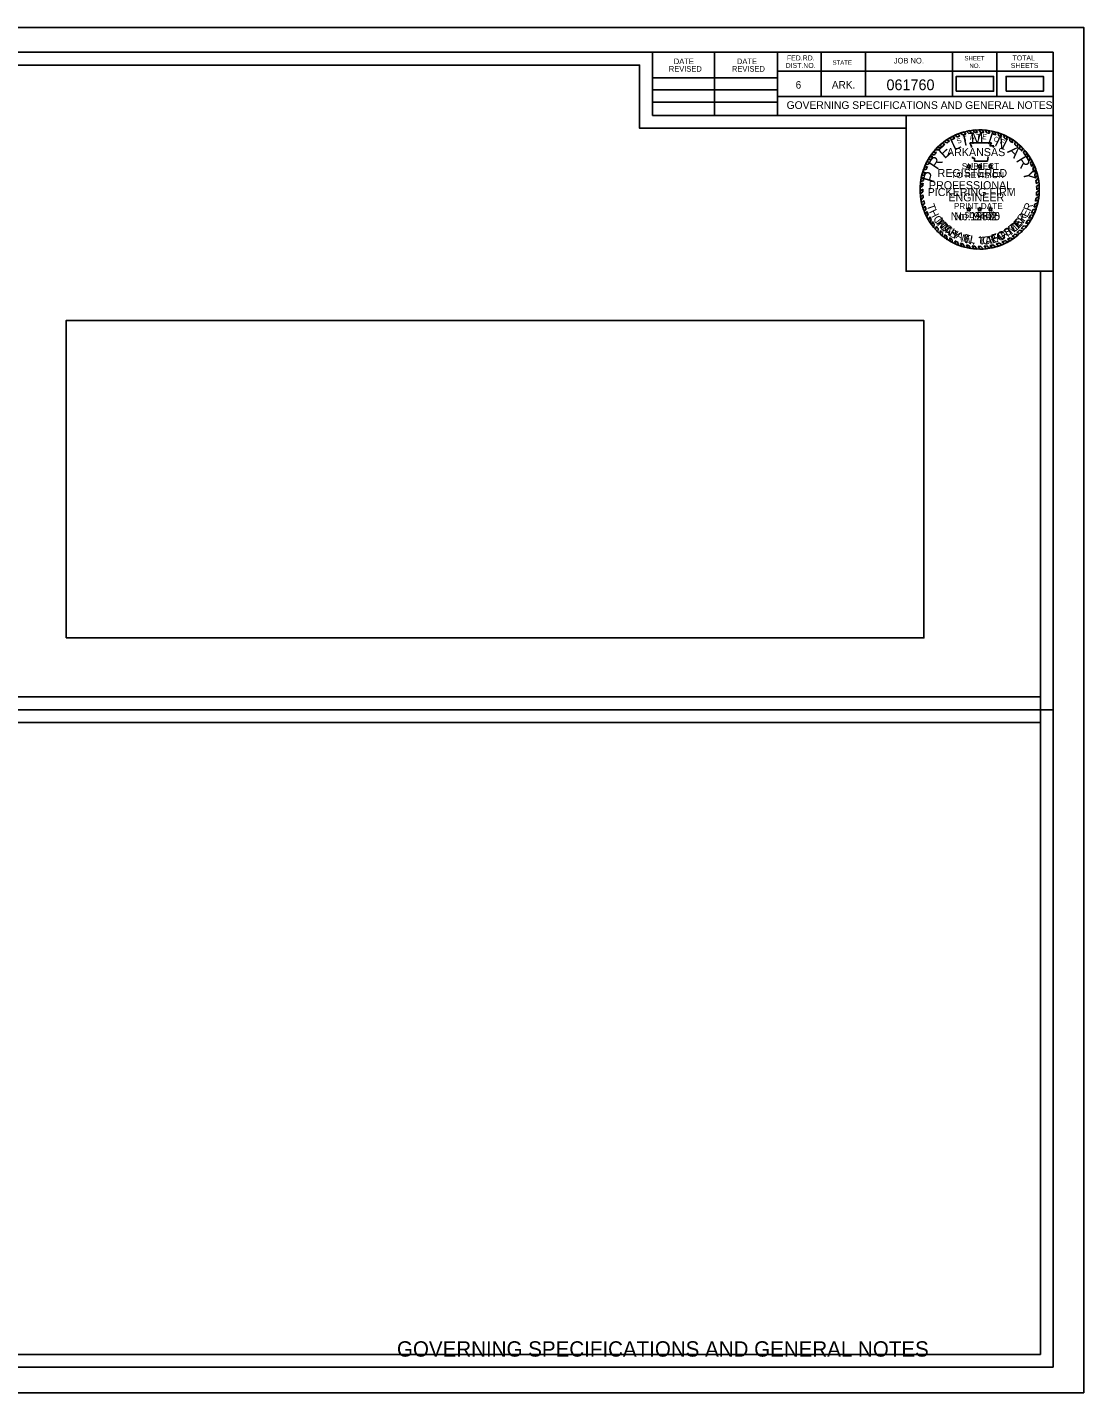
# Model space of a CAD drawing. Extents: x -12 to 321, y -4 to 209.
# Drawn here: x 155.9 to 320.9, y -4 to 209.4 of the extents above; entities that cross this region are included whole.
import ezdxf

# ---------------------------------------------------------------- set-up
doc = ezdxf.new("R2010")
doc.units = 0
for name, color, linetype in [('Default', 7, 'Continuous'), ('R_Border', 7, 'Continuous'), ('R_Border Notes', 7, 'Continuous'), ('R_Border Plan-Plan', 7, 'Continuous'), ('R_Border Title', 7, 'Continuous'), ('R_No Plot', 7, 'Continuous'), ('STAMP_PE_CRAFTON', 7, 'Continuous'), ('STAMP_PE_FOSTER', 7, 'Continuous'), ('STAMP_PE_SEAL-INFO', 7, 'Continuous'), ('STAMP_PE_TAEGTMEYER', 7, 'Continuous'), ('STAMP_PE_TXT', 7, 'Continuous'), ('STAMP_PRELIMINARY', 7, 'Continuous')]:
    doc.layers.add(name, color=color, linetype=linetype)

msp = doc.modelspace()

# ---------------------------------------------------------------- linework, layer by layer
at = {"layer": 'Default'}
for points in [[(301.02, 199.37), (306.86, 199.37), (306.86, 201.68), (301.02, 201.68)], [(308.8, 199.37), (314.64, 199.37), (314.64, 201.68), (308.8, 201.68)], [(161.91, 113.95), (295.96, 113.95), (295.96, 163.53), (161.91, 163.53)]]:
    msp.add_lwpolyline(points, close=True, dxfattribs=at)
at = {"layer": 'R_Border'}
for p, q in [((0, 205.46), (316.18, 205.46)), ((253.54, 195.58), (253.54, 205.46)), ((263.22, 195.58), (263.22, 205.46)), ((273.08, 205.46), (273.08, 195.58)), ((279.92, 205.46), (279.92, 198.52)), ((286.86, 205.46), (286.86, 198.52)), ((300.44, 205.46), (300.44, 198.52)), ((307.38, 205.46), (307.38, 198.52)), ((316.18, 0), (316.18, 205.46)), ((253.54, 201.44), (273.08, 201.44)), ((316.18, 202.52), (273.08, 202.52)), ((316.18, 202.54), (316.18, 202.54)), ((253.54, 199.58), (273.08, 199.58)), ((316.18, 198.52), (273.08, 198.52)), ((276.04, 198.52), (316.18, 198.52)), ((253.54, 197.64), (273.08, 197.64)), ((316.18, 195.58), (253.54, 195.58)), ((316.18, 0), (0, 0))]:
    msp.add_line(p, q, dxfattribs=at)
at = {"layer": 'R_Border Plan-Plan'}
msp.add_line((0, 102.73), (316.18, 102.73), dxfattribs=at)
at = {"layer": 'R_No Plot'}
for points in [[(-12.41, 209.35), (320.93, 209.35), (320.93, -3.98), (-12.41, -3.98)], [(314.18, 104.73), (2, 104.73), (2, 203.46), (251.54, 203.46), (251.54, 193.58), (269.08, 193.58), (293.18, 193.58), (293.18, 171.25), (314.18, 171.25)], [(2, 203.46), (251.54, 203.46), (251.54, 193.58), (269.08, 193.58), (293.18, 193.58), (293.18, 171.25), (314.18, 171.25), (314.18, 2), (2, 2)], [(293.18, 195.58), (316.18, 195.58), (316.18, 171.25), (293.18, 171.25)], [(2, 100.73), (314.18, 100.73), (314.18, 2), (2, 2)]]:
    msp.add_lwpolyline(points, close=True, dxfattribs=at)
at = {"layer": 'STAMP_PE_SEAL-INFO'}
for p, q in [((299.9, 192.03), (300.34, 191.81)), ((300.35, 192.28), (300.82, 192.06)), ((300.78, 192.49), (301.17, 192.22)), ((301.29, 192.71), (301.59, 192.38)), ((301.64, 192.84), (302.02, 192.53)), ((302.23, 193.02), (302.52, 192.67)), ((302.62, 193.11), (302.97, 192.77)), ((303.1, 193.21), (303.4, 192.84)), ((303.62, 193.28), (303.9, 192.9)), ((304.35, 192.93), (304.04, 193.32)), ((304.85, 192.93), (304.57, 193.34)), ((305.31, 192.91), (305.05, 193.34)), ((305.81, 192.86), (305.52, 193.31)), ((306.24, 192.8), (305.98, 193.25)), ((306.8, 192.68), (306.63, 193.14)), ((307.2, 192.57), (307.04, 193.04)), ((307.65, 192.42), (307.51, 192.9)), ((308.07, 192.26), (307.93, 192.76)), ((308.53, 192.06), (308.43, 192.56)), ((308.98, 191.83), (308.89, 192.34)), ((309.37, 191.6), (309.33, 192.1)), ((297.72, 190.22), (298.24, 190.19)), ((298.04, 190.57), (298.59, 190.53)), ((298.38, 190.89), (298.84, 190.75)), ((298.72, 191.19), (299.25, 191.09)), ((299.1, 191.52), (299.55, 191.31)), ((299.52, 191.79), (299.96, 191.58)), ((303.15, 191.31), (306.5, 191.31)), ((303.27, 191.01), (303.15, 191.31)), ((303.38, 190.71), (303.27, 191.01)), ((303.39, 190.59), (303.38, 190.71)), ((306.5, 191.31), (306.27, 190.82)), ((306.27, 190.82), (306.9, 190.82)), ((306.9, 190.82), (306.76, 190.59)), ((309.8, 191.32), (309.77, 191.83)), ((310.16, 191.05), (310.2, 191.54)), ((310.61, 190.68), (310.63, 191.2)), ((310.92, 190.39), (310.99, 190.88)), ((311.28, 190.01), (311.35, 190.54)), ((311.55, 189.7), (311.69, 190.17)), ((296.2, 187.89), (296.7, 187.99)), ((296.38, 188.27), (296.88, 188.34)), ((296.61, 188.7), (297.1, 188.72)), ((296.86, 189.1), (297.38, 189.13)), ((297.1, 189.44), (297.6, 189.44)), ((297.37, 189.81), (297.92, 189.83)), ((303.58, 188.89), (303.55, 189.1)), ((303.89, 188.89), (303.58, 188.89)), ((303.89, 188.46), (303.89, 188.89)), ((305.92, 188.46), (303.89, 188.46)), ((305.94, 188.79), (305.92, 188.46)), ((306.01, 189.1), (305.94, 188.79)), ((311.88, 189.28), (312.01, 189.78)), ((312.1, 188.96), (312.28, 189.43)), ((312.41, 188.47), (312.59, 188.96)), ((312.61, 188.1), (312.83, 188.54)), ((312.84, 187.62), (313.06, 188.1)), ((295.96, 185.89), (295.5, 185.64)), ((295.6, 186.14), (296.07, 186.33)), ((295.7, 186.54), (296.18, 186.71)), ((295.86, 187.05), (296.35, 187.18)), ((296.01, 187.45), (296.52, 187.6)), ((312.98, 187.28), (313.24, 187.71)), ((313.17, 186.73), (313.44, 187.2)), ((313.28, 186.37), (313.57, 186.82)), ((313.41, 185.81), (313.73, 186.25)), ((313.48, 185.43), (313.84, 185.78)), ((295.78, 184.57), (295.36, 184.31)), ((295.77, 184.08), (295.36, 183.74)), ((295.82, 185), (295.38, 184.71)), ((295.77, 183.67), (295.38, 183.35)), ((295.88, 185.43), (295.43, 185.21)), ((313.55, 184.92), (313.92, 185.25)), ((313.58, 184.5), (313.97, 184.79)), ((313.58, 183.58), (314, 183.85)), ((313.59, 183.98), (314, 184.3)), ((295.81, 183.18), (295.44, 182.82)), ((295.86, 182.75), (295.5, 182.37)), ((295.94, 182.29), (295.6, 181.92)), ((296.03, 181.87), (295.72, 181.45)), ((296.15, 181.42), (295.86, 181)), ((313.15, 181.24), (313.64, 181.44)), ((313.29, 181.73), (313.77, 181.93)), ((313.4, 182.18), (313.86, 182.38)), ((313.49, 182.68), (313.93, 182.9)), ((313.54, 183.07), (313.98, 183.33)), ((296.3, 181), (296.01, 180.59)), ((296.46, 180.57), (296.2, 180.15)), ((296.63, 180.19), (296.41, 179.73)), ((296.87, 179.73), (296.68, 179.24)), ((297.1, 179.33), (296.92, 178.86)), ((312.19, 179.23), (312.67, 179.22)), ((312.36, 179.51), (312.87, 179.56)), ((312.64, 180), (313.12, 180.07)), ((312.8, 180.34), (313.29, 180.44)), ((313.01, 180.86), (313.49, 180.99)), ((297.31, 179.01), (297.2, 178.46)), ((297.59, 178.62), (297.49, 178.09)), ((297.89, 178.25), (297.8, 177.73)), ((298.19, 177.91), (298.13, 177.39)), ((298.52, 177.58), (298.49, 177.05)), ((298.86, 177.27), (298.86, 176.74)), ((310.5, 177.27), (310.97, 177.14)), ((310.91, 177.64), (311.35, 177.51)), ((311.16, 177.9), (311.64, 177.82)), ((311.55, 178.34), (312.01, 178.26)), ((311.85, 178.73), (312.36, 178.73)), ((299.22, 176.98), (299.24, 176.45)), ((299.56, 176.73), (299.6, 176.21)), ((299.99, 176.45), (300.05, 175.93)), ((300.34, 176.24), (300.43, 175.73)), ((300.82, 175.99), (300.97, 175.47)), ((301.19, 175.82), (301.36, 175.31)), ((301.68, 175.63), (301.89, 175.13)), ((302.09, 175.49), (302.32, 175)), ((302.6, 175.36), (302.81, 174.89)), ((303, 175.27), (303.24, 174.81)), ((303.5, 175.19), (303.74, 174.75)), ((303.93, 175.14), (304.21, 174.71)), ((304.42, 175.11), (304.72, 174.7)), ((304.88, 175.11), (305.22, 174.72)), ((305.4, 175.14), (305.72, 174.76)), ((305.84, 175.18), (306.21, 174.83)), ((306.28, 175.25), (306.67, 174.91)), ((306.77, 175.36), (307.15, 175.03)), ((307.23, 175.48), (307.65, 175.19)), ((307.73, 175.65), (308.17, 175.38)), ((308.14, 175.81), (308.57, 175.55)), ((308.6, 176.02), (309.09, 175.81)), ((309.01, 176.23), (309.43, 176)), ((309.43, 176.48), (309.88, 176.28)), ((309.77, 176.71), (310.21, 176.52)), ((310.23, 177.05), (310.7, 176.9))]:
    msp.add_line(p, q, dxfattribs=at)
for radius, start, end in [(9.32, 117.6544, 120.8099), (8.91, 115.6869, 119.1583), (9.32, 111.3124, 114.7026), (8.91, 110.3086, 113.1659), (9.32, 105.2339, 109.0352), (8.91, 104.0352, 107.3615), (9.32, 99.7525, 102.7765), (8.91, 98.258, 101.0329), (9.32, 93.9381, 96.5517), (8.91, 92.1102, 95.0367), (9.32, 87.7298, 90.6707), (8.91, 85.9628, 88.9097), (9.32, 81.9732, 84.8236), (8.91, 79.9264, 82.696), (9.32, 75.3125, 77.9426), (8.91, 73.5575, 76.2314), (9.32, 69.6061, 72.3058), (8.91, 67.6248, 70.504), (9.32, 63.1329, 66.2704), (8.91, 61.1558, 64.3784), (9.32, 56.9003, 60.0942), (9.32, 135.4021, 138.3031), (8.91, 133.1331, 136.2562), (9.32, 129.7326, 132.5376), (8.91, 127.5297, 130.9683), (9.32, 123.6199, 126.5906), (8.91, 121.9746, 125.11), (8.91, 54.9238, 58.2702), (8.91, 48.3016, 52.0395), (9.32, 50.3492, 53.7159), (8.91, 42.2212, 45.5512), (9.32, 44.3405, 47.3929), (9.32, 38.1247, 41.2316), (9.32, 152.864, 155.5189), (9.32, 147.0072, 149.899), (8.91, 151.0315, 153.573), (9.32, 141.6056, 144.4486), (8.91, 145.0197, 148.2104), (8.91, 139.301, 142.5873), (8.91, 36.135, 39.5311), (8.91, 29.9032, 33.6645), (9.32, 31.9614, 35.4294), (8.91, 23.7732, 27.2211), (9.32, 25.9391, 29.0125), (9.32, 170.0003, 172.6878), (9.32, 164.3068, 166.894), (9.32, 158.4077, 161.0701), (8.91, 167.9048, 170.9039), (8.91, 162.4331, 165.0013), (8.91, 156.3402, 159.2319), (8.91, 17.6802, 21.4251), (9.32, 19.9538, 23.3141), (8.91, 11.5444, 15.2364), (9.32, 13.8421, 17.4447), (9.32, 7.5852, 10.8621), (9.32, 175.7409, 178.2066), (9.32, 181.7251, 184.1626), (8.91, 179.6454, 182.2633), (8.91, 173.73, 176.4734), (8.91, 5.7599, 9.0606), (8.91, 353.8632, 357.1274), (8.91, 359.7329, 3.0639), (9.32, 1.7215, 4.7268), (9.32, 355.7156, 358.9569), (9.32, 187.4204, 190.1927), (9.32, 193.0369, 195.9973), (8.91, 185.4539, 188.234), (8.91, 191.2274, 193.9858), (8.91, 196.9675, 199.8353), (8.91, 341.777, 345.0925), (8.91, 348.0778, 351.3435), (9.32, 343.8925, 347.035), (9.32, 349.8305, 353.0885), (9.32, 198.8967, 201.6281), (9.32, 204.5479, 207.4328), (8.91, 202.7761, 205.4791), (9.32, 210.8636, 213.6571), (8.91, 208.7883, 211.7934), (8.91, 323.5851, 327.4407), (8.91, 329.5549, 333.2076), (9.32, 325.4405, 328.9872), (8.91, 335.6038, 339.1858), (9.32, 331.4037, 334.9332), (9.32, 337.3837, 340.9933), (9.32, 216.6115, 219.491), (8.91, 214.1838, 217.2747), (9.32, 222.48, 225.3801), (8.91, 220.3909, 223.3056), (8.91, 226.2494, 229.2407), (8.91, 310.7744, 314.3161), (9.32, 312.4518, 315.6633), (8.91, 316.6531, 320.3711), (9.32, 318.2846, 321.8043), (9.32, 228.3665, 231.348), (8.91, 232.229, 234.9336), (9.32, 234.295, 236.9452), (8.91, 238.2223, 240.8353), (9.32, 240.1977, 242.8613), (8.91, 244.3204, 246.9486), (9.32, 246.576, 249.1558), (8.91, 250.3491, 253.1216), (9.32, 252.5967, 255.3252), (8.91, 256.505, 259.1192), (8.91, 262.3783, 265.2012), (8.91, 268.3215, 271.277), (8.91, 274.6157, 277.4486), (8.91, 280.3459, 283.5814), (9.32, 282.3199, 285.3702), (8.91, 286.6423, 289.9783), (9.32, 288.5709, 291.9733), (8.91, 292.8745, 296.1185), (9.32, 294.6481, 298.2166), (8.91, 299.0768, 302.1724), (9.32, 300.621, 303.8703), (8.91, 304.823, 308.5143), (9.32, 306.3721, 310.208), (9.32, 258.4433, 261.1398), (9.32, 264.1978, 267.1009), (9.32, 270.2548, 273.3361), (9.32, 276.4239, 279.4357)]:
    msp.add_arc((304.68, 184.02), radius, start, end, dxfattribs=at)
at = {"layer": 'STAMP_PE_TXT'}
for p, q in [((302.86, 187.59), (302.66, 187.74)), ((302.66, 187.74), (302.91, 187.74)), ((302.91, 187.74), (302.98, 187.97)), ((302.98, 187.97), (303.06, 187.74)), ((303.06, 187.74), (303.3, 187.74)), ((303.3, 187.74), (303.1, 187.59)), ((304.56, 187.59), (304.36, 187.74)), ((304.36, 187.74), (304.6, 187.74)), ((304.6, 187.74), (304.68, 187.97)), ((304.68, 187.97), (304.76, 187.74)), ((304.76, 187.74), (305, 187.74)), ((305, 187.74), (304.8, 187.59)), ((306.26, 187.59), (306.06, 187.74)), ((306.06, 187.74), (306.3, 187.74)), ((306.3, 187.74), (306.38, 187.97)), ((306.38, 187.97), (306.45, 187.74)), ((306.45, 187.74), (306.7, 187.74)), ((306.7, 187.74), (306.5, 187.59)), ((302.78, 187.36), (302.86, 187.59)), ((302.98, 187.5), (302.78, 187.36)), ((303.18, 187.36), (302.98, 187.5)), ((303.1, 187.59), (303.18, 187.36)), ((304.48, 187.36), (304.56, 187.59)), ((304.68, 187.5), (304.48, 187.36)), ((304.88, 187.36), (304.68, 187.5)), ((304.8, 187.59), (304.88, 187.36)), ((306.18, 187.36), (306.26, 187.59)), ((306.38, 187.5), (306.18, 187.36)), ((306.58, 187.36), (306.38, 187.5)), ((306.5, 187.59), (306.58, 187.36)), ((302.86, 180.89), (302.66, 181.03)), ((302.66, 181.03), (302.91, 181.03)), ((302.78, 180.65), (302.86, 180.89)), ((302.98, 180.8), (302.78, 180.65)), ((302.91, 181.03), (302.98, 181.26)), ((302.98, 181.26), (303.06, 181.03)), ((303.18, 180.65), (302.98, 180.8)), ((303.06, 181.03), (303.3, 181.03)), ((303.3, 181.03), (303.1, 180.89)), ((303.1, 180.89), (303.18, 180.65)), ((304.56, 180.89), (304.36, 181.03)), ((304.36, 181.03), (304.6, 181.03)), ((304.48, 180.65), (304.56, 180.89)), ((304.68, 180.8), (304.48, 180.65)), ((304.6, 181.03), (304.68, 181.26)), ((304.68, 181.26), (304.76, 181.03)), ((304.88, 180.65), (304.68, 180.8)), ((304.76, 181.03), (305, 181.03)), ((305, 181.03), (304.8, 180.89)), ((304.8, 180.89), (304.88, 180.65)), ((306.26, 180.89), (306.06, 181.03)), ((306.06, 181.03), (306.3, 181.03)), ((306.18, 180.65), (306.26, 180.89)), ((306.38, 180.8), (306.18, 180.65)), ((306.3, 181.03), (306.38, 181.26)), ((306.38, 181.26), (306.45, 181.03)), ((306.58, 180.65), (306.38, 180.8)), ((306.45, 181.03), (306.7, 181.03)), ((306.7, 181.03), (306.5, 180.89)), ((306.5, 180.89), (306.58, 180.65))]:
    msp.add_line(p, q, dxfattribs=at)
at = {"layer": 'STAMP_PRELIMINARY'}
msp.add_circle((304.68, 184.02), 9.32, dxfattribs=at)

# ---------------------------------------------------------------- texts
at = {"layer": 'R_Border'}
for s, height, p in [('FED.RD.', 0.782, (274.56, 204.18)), ('SHEET', 0.684, (302.3, 204.18)), ('TOTAL', 0.782, (309.82, 204.18)), ('REVISED', 0.879, (256.1, 202.42)), ('DATE', 0.879, (256.88, 203.6)), ('REVISED', 0.879, (265.96, 202.42)), ('DATE', 0.879, (266.74, 203.6)), ('DIST.NO.', 0.782, (274.36, 203)), ('STATE', 0.684, (281.68, 203.5)), ('JOB NO.', 0.879, (291.26, 203.7)), ('NO.', 0.684, (303.08, 203)), ('SHEETS', 0.782, (309.54, 203)), ('6', 1.17, (275.92, 199.78)), ('ARK.', 1.172, (281.58, 199.78))]:
    msp.add_text(s, height=height, dxfattribs=at).set_placement(p)
at = {"layer": 'R_Border Notes'}
for s, height, p in [('061760', 1.68, (290.12, 199.53)), ('GOVERNING SPECIFICATIONS AND GENERAL NOTES', 1.2, (274.51, 196.6))]:
    msp.add_text(s, height=height, dxfattribs=at).set_placement(p)
at = {"layer": 'R_Border Title'}
msp.add_text('GOVERNING SPECIFICATIONS AND GENERAL NOTES', height=2.4, dxfattribs=at).set_placement((213.62, 1.65))
at = {"layer": 'STAMP_PE_CRAFTON'}
for s, rotation, p in [('T', 310.7442, (297.65, 178.92)), ('N', 49.2411, (310.96, 178.04)), ('O', 317.6422, (298.31, 178.11)), ('N', 324.4537, (299.16, 177.32)), ('Y', 331.1686, (300.19, 176.61)), ('A', 20.5125, (307.36, 175.78)), ('F', 28.7821, (308.34, 176.15)), ('T', 34.1136, (309.26, 176.66)), ('O', 41.8391, (310.12, 177.26)), ('N', 347.4752, (302.25, 175.69)), ('.', 356.8926, (303.48, 175.41)), ('C', 6.0117, (305.15, 175.36)), ('R', 14.8189, (306.25, 175.48))]:
    msp.add_text(s, height=1.25, rotation=rotation, dxfattribs=at).set_placement(p)
msp.add_text('No. 12370', height=1.25, dxfattribs=at).set_placement((300.14, 179.22))
at = {"layer": 'STAMP_PE_FOSTER'}
for s, rotation, p in [('M', 308.339, (297.8, 179.04)), ('E', 46.9613, (310.68, 178.01)), ('R', 54.5031, (311.4, 178.83)), ('I', 314.1842, (298.59, 178.11)), ('C', 319.8733, (298.95, 177.75)), ('H', 327.7235, (299.88, 177.02)), ('A', 335.7276, (300.86, 176.44)), ('E', 343.5779, (302, 175.97)), ('F', 15.8691, (306.71, 175.78)), ('O', 23.719, (307.76, 176.1)), ('S', 31.7234, (308.87, 176.63)), ('T', 39.4194, (309.82, 177.26)), ('L', 350.8115, (303.05, 175.69)), ('L', 1.2666, (304.59, 175.53)), ('.', 6.8035, (305.64, 175.59))]:
    msp.add_text(s, height=1.2, rotation=rotation, dxfattribs=at).set_placement(p)
msp.add_text('No. 9402', height=1.25, dxfattribs=at).set_placement((300.67, 179.22))
at = {"layer": 'STAMP_PE_TAEGTMEYER'}
for s, rotation, p in [('T', 289.646, (296.37, 181.53)), ('R', 69.57, (312.63, 180.54)), ('H', 296.7339, (296.73, 180.55)), ('O', 303.7708, (297.33, 179.44)), ('M', 314.2033, (297.98, 178.49)), ('E', 46.8094, (310.72, 177.8)), ('Y', 53.9986, (311.46, 178.61)), ('E', 63.0984, (312.13, 179.56)), ('A', 321.0594, (298.94, 177.52)), ('S', 327.8239, (299.77, 176.88)), ('G', 23.3052, (307.68, 175.88)), ('T', 31.466, (308.78, 176.38)), ('M', 39.3, (309.68, 176.92)), ('N', 344.2727, (301.67, 175.87)), ('.', 350.6464, (302.88, 175.54)), ('T', 3.0061, (304.54, 175.34)), ('A', 8.9826, (305.59, 175.4)), ('E', 17.6836, (306.63, 175.55))]:
    msp.add_text(s, height=1.25, rotation=rotation, dxfattribs=at).set_placement(p)
msp.add_text('No. 19605', height=1.25, dxfattribs=at).set_placement((300.14, 179.22))
at = {"layer": 'STAMP_PE_TXT'}
for s, rotation, p in [('S', 23.5541, (301.28, 191.13)), ('T', 16.311, (302.2, 191.5)), ('A', 9.0679, (303.16, 191.75)), ('T', 1.8248, (304.15, 191.88)), ('E', 355.2002, (305.06, 191.89)), ('O', 342.2506, (306.79, 191.61)), ('F', 335.0075, (307.75, 191.27))]:
    msp.add_text(s, height=0.781, rotation=rotation, dxfattribs=at).set_placement(p)
for s, p in [('ARKANSAS', (299.57, 189.23)), ('REGISTERED', (298.1, 185.96)), ('PROFESSIONAL', (296.75, 184.06)), ('ENGINEER', (299.79, 182.16))]:
    msp.add_text(s, height=1.25, dxfattribs=at).set_placement(p)
at = {"layer": 'STAMP_PRELIMINARY'}
for s, rotation, p in [('I', 12.5248, (302.22, 190.81)), ('M', 3.1074, (303.32, 191.12)), ('I', 342.3164, (305.78, 191.19)), ('N', 333.9382, (306.89, 190.91)), ('E', 42.3578, (299.21, 188.72)), ('L', 25.513, (300.69, 190.05)), ('A', 315.6579, (308.92, 189.89)), ('R', 56.2292, (298.05, 186.99)), ('R', 301.3831, (310.29, 188.57)), ('P', 73.913, (297.5, 184.96)), ('Y', 283.2593, (311.38, 186.79))]:
    msp.add_text(s, height=1.8, rotation=rotation, dxfattribs=at).set_placement(p)
for s, height, p in [('SUBJECT', 0.96, (301.88, 187.17)), ('TO REVISION', 0.96, (300.22, 185.79)), ('PICKERING FIRM', 1.25, (296.55, 182.99)), ('PRINT DATE', 0.96, (300.64, 180.94)), ('$DATE$', 0.96, (302.31, 179.55))]:
    msp.add_text(s, height=height, dxfattribs=at).set_placement(p)

doc.saveas('drawing.dxf')
